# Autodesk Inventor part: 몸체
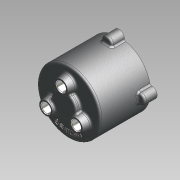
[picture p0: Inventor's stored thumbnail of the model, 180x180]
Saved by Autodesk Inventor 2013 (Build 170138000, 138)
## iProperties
Company: 한국ATC센터
Created: 2014-07
Part Number: 몸체
Document SubType Name: 모델링
Designer: KYOUNG IL JANG
Material: 알루미늄 6061
Mass: 422.438 g
Surface Area: 687.659 cm^2
Volume: 175.481 cm^3
Density: 2.40731 g/cm^3
변환 표준: STEP AP214IS
파일 이름: C:\Users\SeoGD\Desktop\?쒗뿕\紐몄껜.stp
전처리기: Build: 253, Release: 2010 SP1 - Date: Wed 07/29/2009
전송 단위: 밀리미터
불확실성: 0.01
Author: KYOUNG IL JANG
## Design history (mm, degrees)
sketch "스케치2"
  geometry: C1 r 50 at (0, 0); 1 further point
  constraints: 1 centre point, 1 coincident
  dimensions: "d9" = 100 diameter of C1
extrude "돌출2" new body sketch "스케치2" distance "d10" = 80; taper "d11" = 0 deg
feature "쉘1" dims "d12" = 5
sketch "스케치3" dims "d13" = 55
  geometry: C1 r 7.5 at (0, 27.5); C2 r 12.5 at (0, 27.5); 2 further points
  constraints: 2 centre point, 2 coincident, 2 vertical alignment, 2 other
  dimensions: "d14" = 15 diameter of C1; "d15" = 25 diameter of C2
extrude "돌출3" join sketch "스케치3" distance "d16" = 12; taper "d17" = -10 deg
hole "구멍2" diameter "d20" = 15; stored, may be unused: countersink angle "d24" = 90 deg, drill point angle "d26" = 118 deg; dims "d18" = 10, "d19" = 10, "d21" = 6, "d22" = 4, "d23" = 2, "d25" = 15
chamfer "모따기1" distance "d27" = 1; stored, may be unused: second distance "d28" = 2, angle "d29" = 45 deg
sketch "스케치4"
  geometry: L1 (0, 0)-(0, 88); L2 (0, 70)-(13.16, 70); L3 (-45, 75)-(45, 75) reference; L4 (-50, 80)-(50, 80) reference; L5 (13.16, 70)-(14.5, 75); L6 (20, 80)-(20, 88); L7 (20, 88)-(0, 88); L8 (20, 80)-(14.5, 75)
  constraints: 12 end point, 3 point on line, 2 perpendicular, 1 vertical
  dimensions: "d34" = 40 diameter of L6 L1; "d35" = 105 deg angle of L5 L3; "d36" = 5 distance between parallel lines of L2 L3; "d37" = 8 distance between parallel lines of L7 L4; "d51" = 29 diameter of L5.end L1
revolve "회전1" sketch "스케치4" stored, may be unused: angle "d38" = 90 deg
hole "구멍3" diameter "d41" = 15; stored, may be unused: countersink angle "d45" = 90 deg, drill point angle "d47" = 0 deg; dims "d39" = 10, "d40" = 10, "d42" = 6, "d43" = 22, "d44" = 13, "d46" = 15
chamfer "모따기2" distance "d48" = 1; stored, may be unused: second distance "d49" = 2, angle "d50" = 45 deg
fillet "모깎기1" dims "d52" = 3
fillet "모깎기2" dims "d53" = 3, "d72" = 0.2
sketch "스케치5"
  geometry: A1 r 50 centre (0, 0) between (50, 0) and (-8.074, 49.344) reference; A2 r 8.5 centre (0, 52) between (8.074, 49.344) and (-8.074, 49.344); 1 further point
  constraints: 5 point on circle, 1 centre point, 1 horizontal alignment
  dimensions: "d54" = 90 deg dimension on point (0, 0) A2.centre A1.start; "d55" = 52 distance of A2.centre point (0, 0); "d56" = 17 diameter of A2
extrude "돌출4" join sketch "스케치5" distance "d57" = 20; taper "d58" = 0 deg
fillet "모깎기3" dims "d59" = 3
hole "구멍4" diameter "d62" = 4.134; stored, may be unused: countersink angle "d66" = 90 deg, drill point angle "d68" = 118 deg; dims "d60" = 10, "d61" = 10, "d63" = 12, "d64" = 22, "d65" = 13, "d67" = 15
sketch "스케치6"
  geometry: C1 r 47 at (0, 0) reference; C2 r 42.5 at (0, 0); 1 further point
  constraints: 1 centre point, 1 coincident, 1 other
  dimensions: "d73" = 85 diameter of C2
feature "엠보싱1" sketch "스케치6" dims "d74" = 1, "d75" = 0
node "솔리드1"
node "솔리드 본체"
node "곡면 본체"
pattern_circular "원형 패턴1" dims "d31" = 360 deg
pattern_circular "원형 패턴2" dims "d70" = 360 deg
node "솔리드2"
